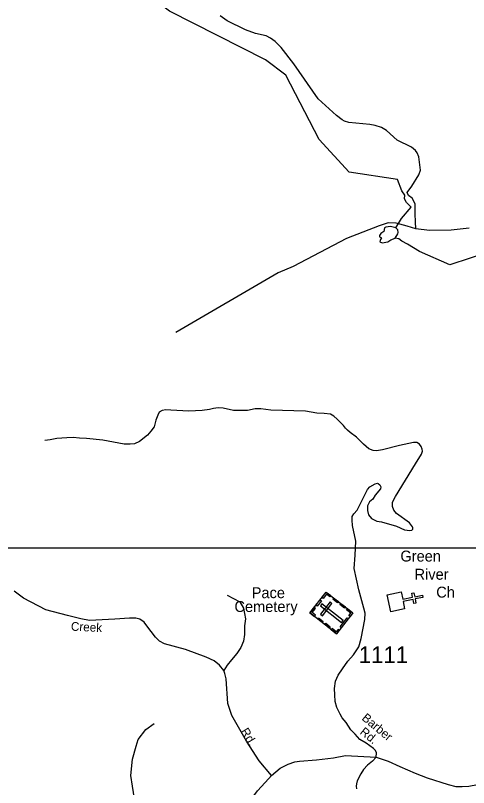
# Model space of a CAD drawing. Extents: x 884530 to 1028605, y 526725 to 653634.
# Drawn here: x 964663 to 968072, y 549354 to 555159 of the extents above; entities that cross this region are included whole.
import ezdxf

# ---------------------------------------------------------------- set-up
doc = ezdxf.new("R2010")
doc.units = 0
for name, color, linetype in [('Exist Cultural Cemetery CELL', 7, 'Continuous'), ('Exist Cultural Cemetery Label', 7, 'Continuous'), ('Exist Cultural Church CELL', 7, 'Continuous'), ('Exist Cultural Church Label', 7, 'Continuous'), ('Exist Hydrographic Creek Single Shore', 7, 'Continuous'), ('Exist Hydrographic Pond Over 1500 Sq Ft', 7, 'Continuous'), ('Exist Road Non-System Type 51', 7, 'Continuous'), ('Exist Road Secondary Type 51 Attributed', 7, 'Continuous'), ('Exist Road Secondary Type 51 Label', 7, 'Continuous'), ('Exist Road Secondary Type 51 Number Label', 7, 'Continuous'), ('Map Preparation Inset Cut Line', 7, 'Continuous')]:
    doc.layers.add(name, color=color, linetype=linetype)

msp = doc.modelspace()

# ---------------------------------------------------------------- linework, layer by layer
at = {"layer": 'Exist Cultural Cemetery CELL'}
for points in [[(966878.5, 550666.7), (967001, 550823.6), (967201.7, 550667), (967079.3, 550510)], [(967035.2, 550797), (967028.3, 550788.1), (967002.9, 550807.9), (966977.9, 550775.9), (966969.2, 550782.7), (967001.1, 550823.6)], [(966924.1, 550725.1), (966956, 550765.9), (966965, 550758.9), (966933.1, 550718)], [(967085.8, 550743), (967051.7, 550769.7), (967058.7, 550778.7), (967092.8, 550752)], [(966912.7, 550640), (966919.6, 550649), (966894.3, 550668.8), (966919.2, 550700.7), (966910.5, 550707.6), (966878.5, 550666.7)], [(966968.7, 550734.6), (966957.2, 550719.9), (967117.1, 550595.1), (967128.6, 550609.8)], [(966957.3, 550657), (966972, 550645.5), (967044.4, 550738.3), (967029.7, 550749.8)], [(967137.8, 550702.5), (967103.6, 550729.1), (967110.6, 550738.1), (967144.8, 550711.4)], [(967181.4, 550640.8), (967172.3, 550647.9), (967185.8, 550665.2), (967154, 550690.1), (967160.8, 550698.9), (967201.7, 550667)], [(966971.1, 550594.4), (966937, 550621), (966944, 550630), (966978.1, 550603.4)], [(967024.1, 550553), (966989.9, 550579.7), (966997, 550588.6), (967031.1, 550562)], [(967105.5, 550562.4), (967157.8, 550629.3), (967166.7, 550622.2), (967114.5, 550555.4)], [(967099.6, 550536.1), (967090.5, 550543.2), (967077, 550525.8), (967045.1, 550550.7), (967038.3, 550541.9), (967079.2, 550510)]]:
    msp.add_lwpolyline(points, close=True, dxfattribs=at)
at = {"layer": 'Exist Cultural Church CELL'}
msp.add_lwpolyline([(967564.9, 550825.2), (967576.3, 550769.4), (967650.9, 550784.5), (967644.6, 550815.9), (967660.2, 550819.1), (967666.6, 550787.7), (967725.5, 550799.7), (967728.7, 550783.9), (967669.8, 550772), (967676.1, 550740.6), (967660.5, 550737.5), (967654.1, 550768.8), (967579.5, 550753.7), (967590.8, 550697.2), (967486.5, 550676.1), (967460.6, 550804.1)], close=True, dxfattribs=at)
at = {"layer": 'Exist Hydrographic Creek Single Shore'}
for points in [[(967523.6, 553562.1), (967567.8, 553633.2), (967640.2, 553716.8), (967604.3, 553752.5), (967589, 553779.4), (967592.8, 553808.3), (967569.7, 553840.9), (967538, 553926.1), (967173.1, 553979.8), (966948.1, 554227.2), (966698.3, 554711.4), (966543.7, 554826.1), (965822.5, 555191.8), (965660.1, 555316.5)], [(969607.9, 552637.4), (969601.8, 552648.6), (969588.4, 552723.6), (969458.2, 552781.8), (969223.2, 552973.6), (968800.9, 553064.2), (968483.8, 553300.3), (968236.7, 553384.1), (967931.2, 553285.2), (967702.9, 553385), (967613, 553439.3), (967569.7, 553462.1), (967546.7, 553479.4), (967519.8, 553485.2)]]:
    msp.add_lwpolyline(points, dxfattribs=at)
at = {"layer": 'Exist Hydrographic Pond Over 1500 Sq Ft'}
msp.add_lwpolyline([(967421.7, 553448.6), (967464, 553458.2), (967487.1, 553471.7), (967519.8, 553485.2), (967540.9, 553517.9), (967542.8, 553527.5), (967540.9, 553546.7), (967523.6, 553562.1), (967485.1, 553571.7), (967450.5, 553567.9), (967439, 553562.1), (967435.2, 553535.2), (967412.1, 553519.8), (967400.6, 553504.4), (967400.6, 553494.8), (967417.9, 553487.1), (967408.2, 553475.5), (967406.3, 553467.9), (967404.4, 553458.2)], close=True, dxfattribs=at)
at = {"layer": 'Exist Road Non-System Type 51'}
for points in [[(967675, 553554.8), (967671.6, 553608.2), (967669.7, 553667.9), (967669.7, 553742.9), (967646.6, 553785.2), (967619.7, 553806.3), (967610.1, 553827.5), (967644.7, 553875.6), (967698.5, 553960.2), (967710.1, 553994.8), (967697.1, 554097.2), (967684.3, 554127.1), (967673, 554142.9), (967642.4, 554167.8), (967533.8, 554221.7), (967455, 554293.2), (967417.6, 554315.8), (967369, 554331.5), (967329.1, 554339.5), (967170.1, 554355), (967138.7, 554363.2), (967119.9, 554373.4), (967077.6, 554406.8), (966939.9, 554531.9), (966756.4, 554795.3), (966661.2, 554919.4), (966618.1, 554963.3), (966581.6, 554989.5), (966549, 555006.7), (966468.4, 555024.6), (966393.1, 555051.7), (966257.1, 555117.8), (966203.2, 555155.9)], [(967398.1, 553578), (967154.5, 553481.3), (966752.7, 553271.7), (966639.2, 553223.6), (965870.1, 552775.4)], [(966152.5, 552203), (966122.5, 552195.4), (966067.6, 552188), (965968.4, 552182.6), (965876.7, 552187.7), (965832, 552190.2), (965793.9, 552192.8), (965767.1, 552189), (965745.5, 552176.2), (965735.2, 552153.3), (965720, 552115.1), (965707.2, 552066.7), (965681.7, 552032.3), (965656.1, 552004.4), (965596.2, 551954.6), (965559.7, 551938.2), (965525.5, 551934.8), (965481.3, 551936.1), (965321.6, 551966.3), (965199.1, 551979.5), (965146.4, 551981.8), (965096.8, 551984.7), (965049.9, 551982.6), (964974.8, 551977.5), (964923.8, 551967.3), (964884.3, 551963.5)], [(967263.4, 550474.6), (967292.7, 550616.9), (967295, 550665.9), (967283.8, 550703.7), (967246, 550839.3), (967210.5, 551001.7), (967219.3, 551101.8), (967223.7, 551206.2), (967199.3, 551324.1), (967195.1, 551363.5), (967197, 551390.8), (967209.1, 551411.9), (967233.5, 551438.9), (967310.5, 551594.6), (967329, 551616), (967368, 551637.3), (967385.6, 551642.2), (967392.1, 551640.8), (967404.5, 551630.6), (967411.7, 551615.7), (967409, 551599.1), (967369.6, 551552.3), (967350.9, 551521.8), (967326, 551502), (967312.3, 551473.1), (967312.7, 551437.5), (967319.4, 551404.2), (967341.6, 551377.5), (967381.6, 551357.5), (967415.9, 551351), (967528.6, 551318.4), (967590.6, 551290.6), (967631.1, 551286.3), (967644.6, 551288.9), (967652.7, 551295.7), (967653.7, 551306.8), (967650.7, 551314.8), (967628, 551344.9), (967530.7, 551415.3), (967508.4, 551439.8), (967499.5, 551466.5), (967499.5, 551499.8), (967521.7, 551542.1), (967673, 551786.6), (967718.5, 551859.5), (967725, 551883.4), (967722.6, 551897.1), (967714.1, 551918.7), (967702.7, 551936.1), (967682.2, 551947.5), (967657.3, 551947.6), (967552.3, 551926.7), (967424.5, 551892.2), (967379.9, 551885.8), (967354.4, 551887.1), (967322.5, 551901.1), (967281.7, 551935.5), (967229.5, 551989), (967181.2, 552022.7), (967162, 552039.9), (967145.5, 552056.9), (967131.4, 552076.9), (967084.3, 552124), (967057.6, 552146.9), (967032.1, 552160.9), (966986.3, 552167.3), (966931.4, 552169.9), (966844.8, 552184.2), (966585, 552190.2), (966508.5, 552200.4), (966467.8, 552201.8), (966407.9, 552187.7), (966304.7, 552187.7), (966227, 552205.6), (966187.5, 552209.4), (966152.5, 552203)], [(966256.7, 550801.5), (966350.2, 550750.5), (966378.5, 550702.3), (966392.7, 550622.9), (966387, 550569.1), (966387, 550503.9), (966378.5, 550455.7), (966358.7, 550407.6), (966328.6, 550361), (966289.1, 550315.3), (966256.8, 550274.9), (966231.7, 550232.7)], [(965619.8, 549093.1), (965590.3, 549155.6), (965566.3, 549221.3), (965543, 549364), (965531.9, 549443.4), (965543.1, 549566.7), (965570.6, 549664.5), (965586.2, 549715.3), (965644.9, 549789.7), (965707.6, 549836.6)], [(967377.2, 549581.4), (967349.7, 549551.6), (967310.5, 549522.9), (967280.9, 549489.6), (967261.5, 549456.2), (967234.9, 549405), (967228.8, 549382.1), (967227.1, 549363.7), (967228.2, 549343.2)]]:
    msp.add_lwpolyline(points, dxfattribs=at)
at = {"layer": 'Exist Road Secondary Type 51 Attributed'}
for points in [[(968075.5, 553560.7), (967940.2, 553544.2), (967777.4, 553542.9), (967675, 553554.8), (967609.6, 553576), (967527.4, 553598.6), (967468.2, 553600.5), (967398.1, 553578)], [(966589.2, 549443.6), (966496.4, 549555.8), (966402.6, 549703.5), (966291.8, 549895.2), (966261.3, 549986.7), (966249.2, 550171.2), (966239.3, 550210.7), (966231.7, 550232.7), (966197.6, 550273.1), (966158.1, 550307.2), (966097.1, 550335), (965941.8, 550390.7), (965783.9, 550434.6), (965746.2, 550454.4), (965716.6, 550485.8), (965652.8, 550570.2), (965630.9, 550598.5), (965598.5, 550620), (965568.9, 550628.1), (965522.3, 550628.1), (965411.3, 550619.2), (965219.2, 550609.6), (965156.1, 550621.8), (965054.7, 550646.9), (964890.9, 550690.5), (964725.1, 550777.4), (964654.5, 550831)], [(967377.2, 549581.4), (967378.9, 549614.4), (967372.2, 549632.7), (967356.8, 549648.1), (967301, 549687.5), (967254.8, 549714.5), (967218.2, 549754), (967187.4, 549788.6), (967150.8, 549843), (967121, 549878.7), (967105.6, 549906.6), (967081.5, 549956.6), (967068.1, 550000.9), (967065.2, 550051), (967063.3, 550098.7), (967071, 550152.6), (967091.2, 550198.8), (967124.7, 550247.4), (967164.3, 550305.2), (967206.6, 550352.4), (967245.1, 550413), (967263.4, 550474.6)], [(966589.2, 549443.6), (966653.9, 549499.9), (966715.8, 549530.3), (966766.1, 549547.3), (966799.6, 549551.9), (966928.6, 549563.3), (967056.4, 549578.3), (967146.3, 549593.8), (967377.2, 549581.4)], [(967377.2, 549581.4), (967467.4, 549552.7), (967555, 549513.3), (967669.8, 549461.2), (967760.4, 549426.1), (967917.9, 549376.3), (967977.1, 549362), (968023.8, 549361.1), (968073.7, 549365), (968138.4, 549377.6), (968182.3, 549386.6), (968226.3, 549399.2), (968358.2, 549468.3)], [(965521.4, 549017.3), (965566.5, 549062.7), (965619.8, 549093.1), (965656.9, 549103), (965703.5, 549109.3), (965767.8, 549108.6), (965838.6, 549088.2), (965902.3, 549060.4), (966014.9, 548990.8), (966076.9, 548955.8), (966118.1, 548948.6), (966143.3, 548951.3), (966167.5, 548959.4), (966203.4, 548978.2), (966232.4, 548998.4), (966276.1, 549050.9), (966346, 549143.9), (966483.3, 549329.6), (966570.6, 549421.5), (966589.2, 549443.6)]]:
    msp.add_lwpolyline(points, dxfattribs=at)
at = {"layer": 'Map Preparation Inset Cut Line'}
msp.add_lwpolyline([(1000725.2, 565640.1), (964100.1, 565640.1), (964100.1, 551156.3), (1000725.2, 551156.3)], close=True, dxfattribs=at)

# ---------------------------------------------------------------- texts
at = {"layer": 'Exist Cultural Cemetery Label'}
for s, p in [('Pace', (966440.6, 550777.8)), ('Cemetery', (966310.7, 550674))]:
    msp.add_text(s, height=82.02, dxfattribs=at).set_placement(p)
at = {"layer": 'Exist Cultural Church Label'}
for s, p in [('Green', (967559, 551053.2)), ('River', (967665.3, 550916.4)), ('Ch', (967828.7, 550782))]:
    msp.add_text(s, height=82.02, dxfattribs=at).set_placement(p)
at = {"layer": 'Exist Road Secondary Type 51 Label'}
for s, rotation, p in [('Creek', 357.37824, (965079.6, 550533.6)), ('Barber ', 320.34408, (967263.5, 549867.7)), ('Rd.', 301.29141, (966355.1, 549777.7)), ('Rd.', 321.57025, (967248.8, 549761.6))]:
    msp.add_text(s, height=65.62, rotation=rotation, dxfattribs=at).set_placement(p)
at = {"layer": 'Exist Road Secondary Type 51 Number Label'}
msp.add_text('1111', height=125, dxfattribs=at).set_placement((967245.5, 550290.3))

doc.saveas('drawing.dxf')
